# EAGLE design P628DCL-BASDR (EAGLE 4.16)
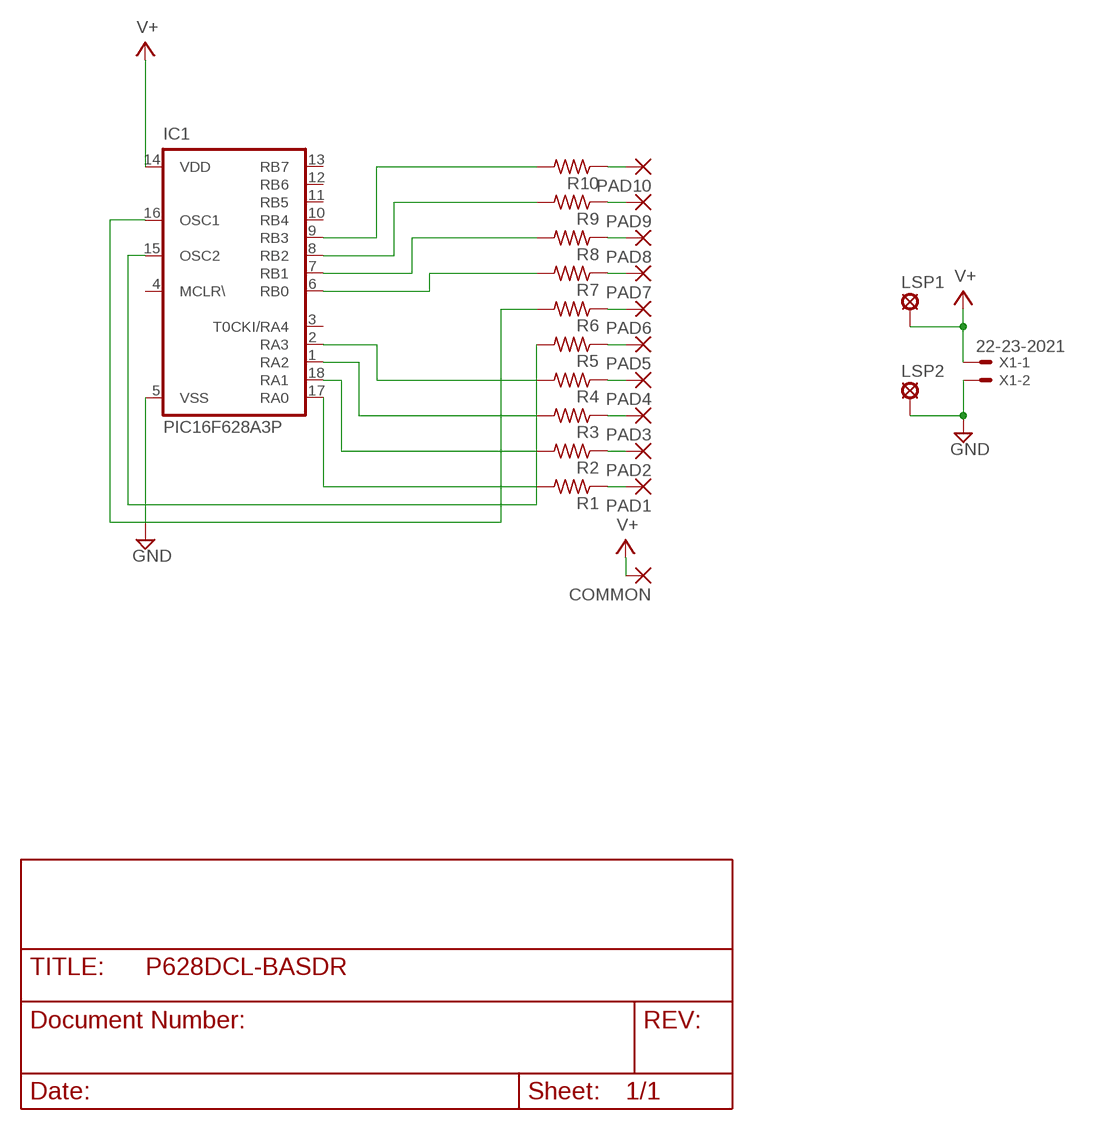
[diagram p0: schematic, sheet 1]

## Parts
COMMON  1,6/0,8  [1,6/0,8]
IC1  PIC16F628A3P  [DIL18]
LSP1  LSP10  [LSP10]
LSP2  LSP10  [LSP10]
PAD1  1,6/0,8  [1,6/0,8]
PAD2  1,6/0,8  [1,6/0,8]
PAD3  1,6/0,8  [1,6/0,8]
PAD4  1,6/0,8  [1,6/0,8]
PAD5  1,6/0,8  [1,6/0,8]
PAD6  1,6/0,8  [1,6/0,8]
PAD7  1,6/0,8  [1,6/0,8]
PAD8  1,6/0,8  [1,6/0,8]
PAD9  1,6/0,8  [1,6/0,8]
PAD10  1,6/0,8  [1,6/0,8]
R1  R-US_0204/7  [0204/7]
R2  R-US_0204/7  [0204/7]
R3  R-US_0204/7  [0204/7]
R4  R-US_0204/7  [0204/7]
R5  R-US_0204/7  [0204/7]
R6  R-US_0204/7  [0204/7]
R7  R-US_0204/7  [0204/7]
R8  R-US_0204/7  [0204/7]
R9  R-US_0204/7  [0204/7]
R10  R-US_0204/7  [0204/7]
X1  22-23-2021  [22-23-2021]

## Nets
GND: IC1.5(VSS) LSP2.MP X1.2
N$1: IC1.15(OSC2) R5.2
N$2: PAD10.1(P) R10.1
N$3: PAD9.1(P) R9.1
N$4: PAD8.1(P) R8.1
N$5: PAD7.1(P) R7.1
N$6: PAD6.1(P) R6.1
N$7: PAD5.1(P) R5.1
N$8: PAD4.1(P) R4.1
N$9: PAD3.1(P) R3.1
N$10: PAD2.1(P) R2.1
N$11: PAD1.1(P) R1.1
N$14: IC1.16(OSC1) R6.2
N$17: IC1.17(RA0) R1.2
N$18: IC1.18(RA1) R2.2
N$19: IC1.1(RA2) R3.2
N$20: IC1.2(RA3) R4.2
N$23: IC1.9(RB3) R10.2
N$24: IC1.8(RB2) R9.2
N$25: IC1.7(RB1) R8.2
N$26: IC1.6(RB0) R7.2
V+: COMMON.1(P) IC1.14(VDD) LSP1.MP X1.1
Unconnected: IC1.3(T0CKI/RA4) IC1.4(MCLR\) IC1.10(RB4) IC1.11(RB5) IC1.12(RB6) IC1.13(RB7)

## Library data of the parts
COMMON PAD1-PAD10 = wirepad:1,6/0,8: THROUGH-HOLE PAD
IC1 = microchip:PIC16F628A: MICROCONTROLLER 8-Bit PIC16F8X Family - CMOS Flash/EEPROM Pin Compatible : PIC16F83, PIC16CR83, PIC16F84A, PIC16CR84 see also PIC16C*
LSP1 LSP2 = solpad:LSP10: SOLDER PAD
R1-R10 = rcl:R-US_: RESISTOR, American symbol
X1 = con-molex:22-23-2021: .100" (2.54mm) Center Header - 2 Pin

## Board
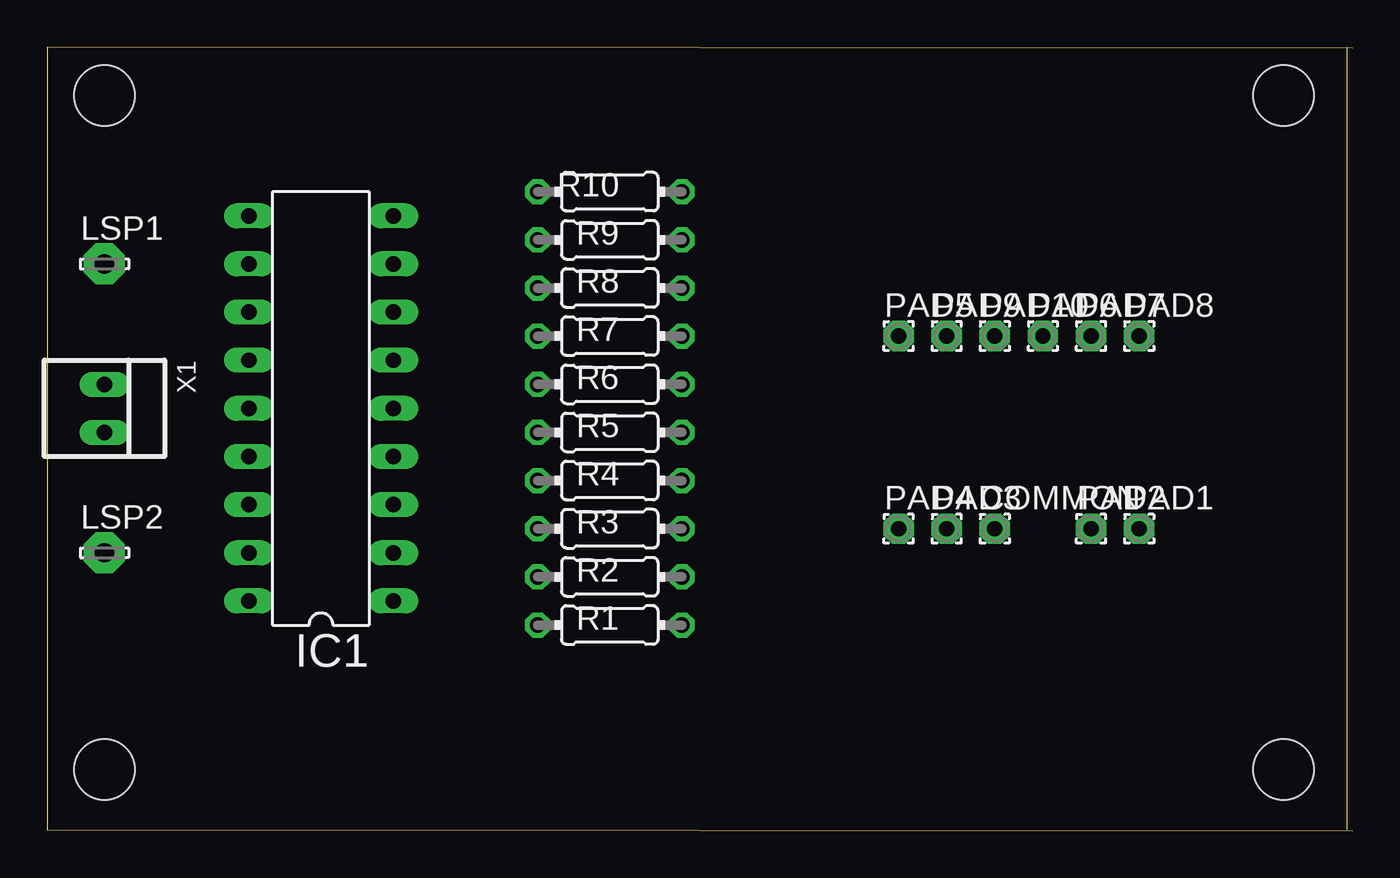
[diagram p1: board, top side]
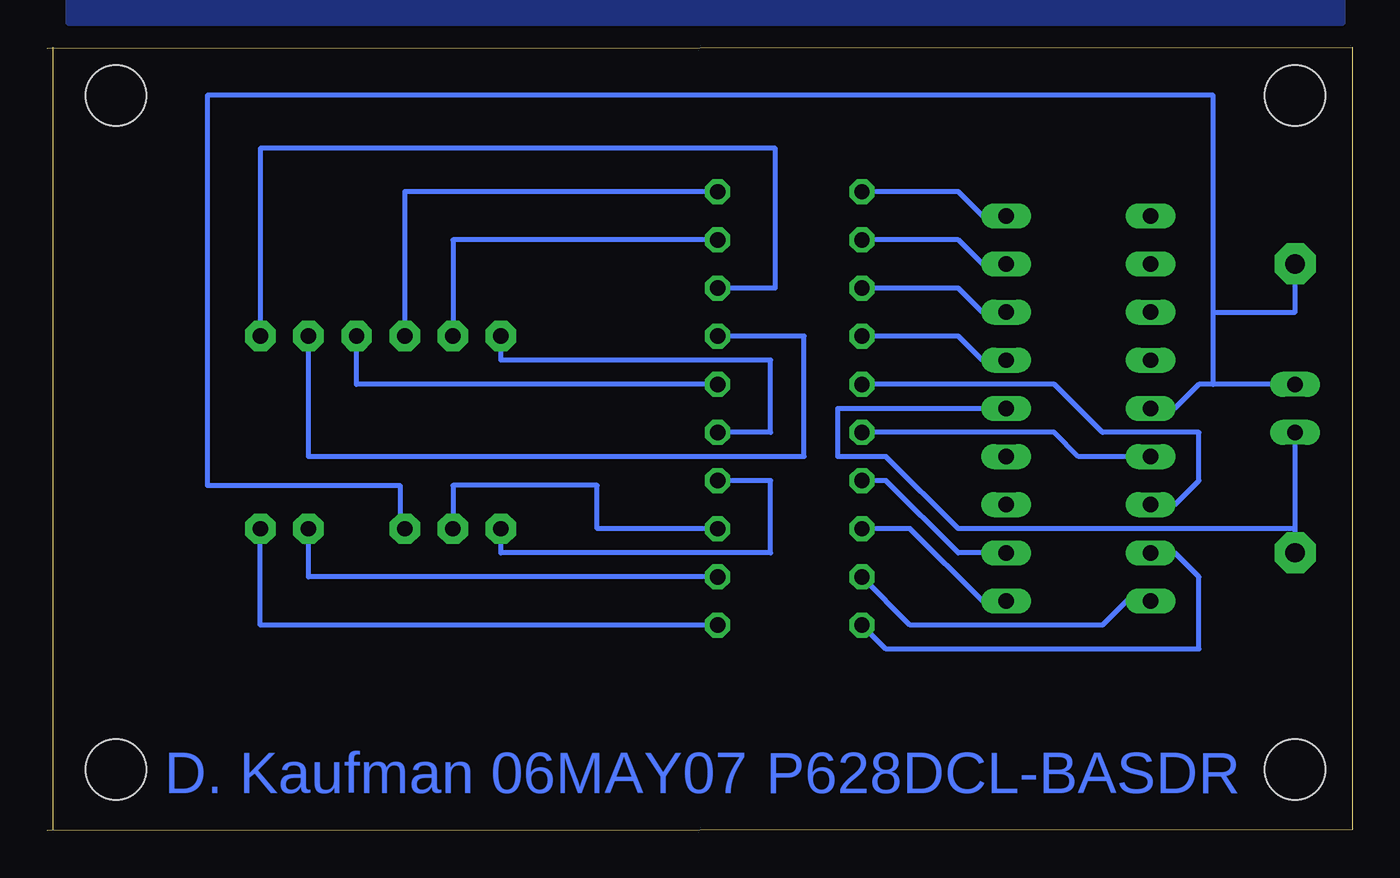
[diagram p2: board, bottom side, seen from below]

Size 68.86 x 41.32 mm. Coordinates in mm from the lower left corner, seen from the top.
Outline: 68.86,0 0,0.05 0,41.32 68.86,41.26
Outline: 68.58,41.32 68.58,0.05
Copper layers (1*16): Top 0.035mm / dielectric 1.5mm / Bottom 0.035mm
Design rules "default": minimum track width 10mil, minimum drill 24mil, track to track 8mil, track to pad 8mil, pad to pad 8mil, via to via 8mil, smd to smd 8mil, copper to edge 40mil, drill to drill 8mil, minimum pad ring 10mil, minimum via ring 8mil, stop-mask expansion 4mil, vias tented up to drill 0mil, thermal gap 10mil
Holes 3.2 mm at 3.01,38.78 3.01,3.22 65.24,38.78 65.24,3.22

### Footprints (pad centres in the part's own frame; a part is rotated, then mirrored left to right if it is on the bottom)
1,6/0,8 = drill 0.813 pad 1.6 octagon: 1 0,0
DIL18 = drill 0.813 long: 1 -10.16,-3.81; 2 -7.62,-3.81; 3 -5.08,-3.81; 4 -2.54,-3.81; 5 0,-3.81; 6 2.54,-3.81; 7 5.08,-3.81; 8 7.62,-3.81; 9 10.16,-3.81; 10 10.16,3.81; 11 7.62,3.81; 12 5.08,3.81; 13 2.54,3.81; 14 0,3.81; 15 -2.54,3.81; 16 -5.08,3.81; 17 -7.62,3.81; 18 -10.16,3.81
LSP10 = drill 1.016 pad 2.159 octagon: MP 0,0
0204/7 = drill 0.813 octagon: 1 -3.81,0; 2 3.81,0
22-23-2021 = drill 0.813 long: 1 -1.27,0; 2 1.27,0

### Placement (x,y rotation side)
COMMON  50,15.92 0 top
IC1  14.44,22.27 90 top
LSP1  3.01,29.89 0 top
LSP2  3.01,14.65 0 top
PAD1  57.62,15.92 0 top
PAD2  55.08,15.92 0 top
PAD3  47.46,15.92 0 top
PAD4  44.92,15.92 0 top
PAD5  44.92,26.08 0 top
PAD6  52.54,26.08 0 top
PAD7  55.08,26.08 0 top
PAD8  57.62,26.08 0 top
PAD9  47.46,26.08 0 top
PAD10  50,26.08 0 top
R1  29.68,10.84 180 top
R2  29.68,13.38 180 top
R3  29.68,15.92 180 top
R4  29.68,18.46 180 top
R5  29.68,21 180 top
R6  29.68,23.54 180 top
R7  29.68,26.08 180 top
R8  29.68,28.62 180 top
R9  29.68,31.16 180 top
R10  29.68,33.7 180 top
X1  3.01,22.27 270 top

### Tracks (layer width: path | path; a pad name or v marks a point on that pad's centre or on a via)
GND
  Bottom 0.254: LSP2.MP 3.01,15.92 | 3.01,15.92 X1.2 | IC1.5 27.14,22.27 27.14,19.73 24.6,19.73 20.79,15.92 3.01,15.92
N$1
  Bottom 0.254: R5.2 15.71,21 14.44,19.73 IC1.15
N$2
  Bottom 0.254: R10.1 50,33.7 PAD10.1
N$3
  Bottom 0.254: PAD9.1 47.46,31.16 33.74,31.16 | 33.74,31.16 R9.1 | 33.74,30.91 33.74,31.16
N$4
  Bottom 0.254: R8.1 30.44,28.62 30.44,35.99 57.62,35.99 PAD8.1 57.62,25.83
N$5
  Bottom 0.254: R7.1 28.92,26.08 28.92,19.73 55.08,19.73 PAD7.1
N$6
  Bottom 0.254: R6.1 52.54,23.54 PAD6.1
N$7
  Bottom 0.254: R5.1 30.7,21 30.7,24.81 44.92,24.81 PAD5.1
N$8
  Bottom 0.254: R4.1 30.7,18.46 30.7,14.65 44.92,14.65 PAD4.1
N$9
  Bottom 0.254: R3.1 39.84,15.92 39.84,18.21 47.46,18.21 PAD3.1
N$10
  Bottom 0.254: 34,13.13 34,13.38 R2.1 55.08,13.38 PAD2.1
N$11
  Bottom 0.254: PAD1.1 57.62,10.84 R1.1
N$12
  pour Bottom: 0.47,60.37 67.78,60.37 67.78,42.59 0.47,42.59
N$14
  Bottom 0.254: R6.2 15.71,23.54 13.17,21 8.09,21 8.09,18.46 9.36,17.19 IC1.16
N$17
  Bottom 0.254: R1.2 24.6,9.57 8.09,9.57 8.09,13.38 9.36,14.65 IC1.17
N$18
  Bottom 0.254: R2.2 23.33,10.84 13.17,10.84 11.9,12.11 IC1.18
N$19
  Bottom 0.254: R3.2 23.33,15.92 19.52,12.11 IC1.1
N$20
  Bottom 0.254: R4.2 24.6,18.46 20.79,14.65 IC1.2
N$23
  Bottom 0.254: R10.2 20.79,33.7 19.52,32.43 IC1.9
N$24
  Bottom 0.254: R9.2 20.79,31.16 19.52,29.89 IC1.8
N$25
  Bottom 0.254: R8.2 20.79,28.62 19.52,27.35 IC1.7
N$26
  Bottom 0.254: R7.2 20.79,26.08 19.52,24.81 IC1.6
V+
  Bottom 0.254: IC1.14 9.36,22.27 8.09,23.54 7.33,23.54 | COMMON.1 50.25,15.92 50.25,18.21 60.41,18.21 60.41,38.78 7.33,38.78 7.33,27.35 | 7.33,23.54 7.33,27.35 | X1.1 7.33,23.54 | LSP1.MP 3.01,27.35 7.33,27.35

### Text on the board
Bottom: P628DCL-BASDR | D. Kaufman 06MAY07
